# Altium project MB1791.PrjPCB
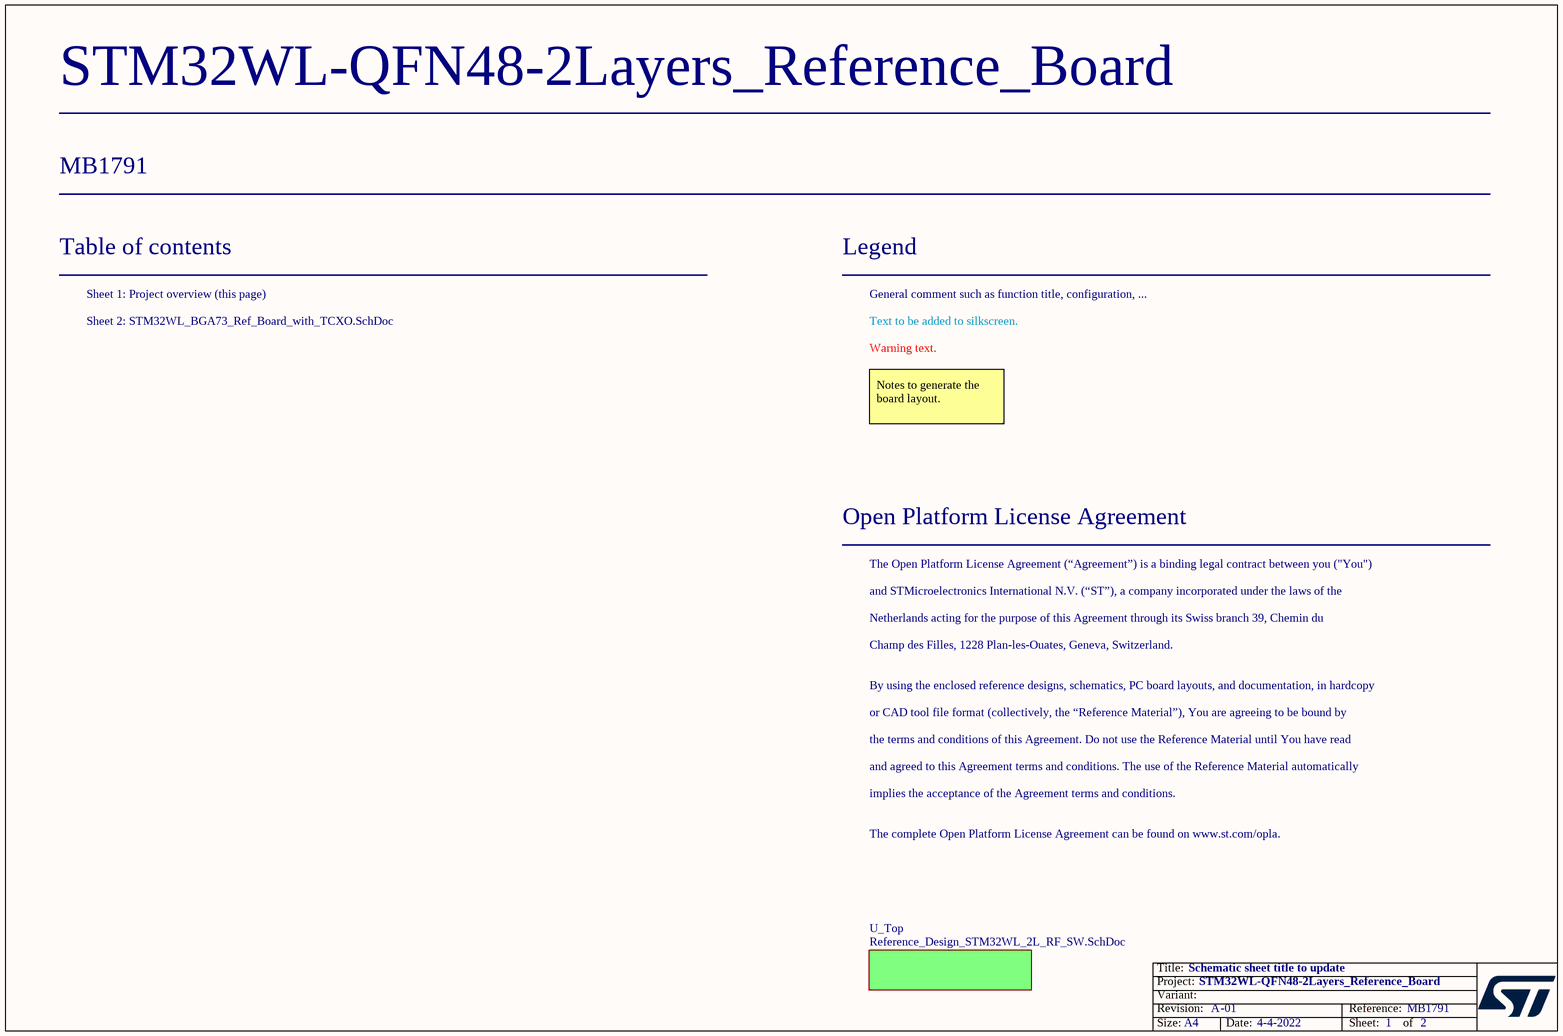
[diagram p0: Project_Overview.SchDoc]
Board_Assembly_Revision: 01; Board_Document_Date: 4-4-2022; Board_Name: STM32WL-QFN48-2Layers_Reference_Board; Board_PCB_Revision: A; Board_Reference: MB1791
2 sheets, 87 parts. Net scope: flat (ports and power ports of the same name join across sheets).
Board file: MB1791.PcbDoc
Sheets:
  Project_Overview.SchDoc
    U_Top = Reference_Design_STM32WL_2L_RF_SW.SchDoc

## Sheet Project_Overview.SchDoc: Schematic sheet title to update
size A4; Date: Not used; ApprovedBy: Not used; CheckedBy: Not used; Author: Not used; CompanyName: STMicroelectronics; DrawnBy: Not used; Engineer: Not used; Organization: Not used; Address1: Not used; Address2: Not used; Address3: Not used; Address4: Not used; DocumentNumber: Not used; Revision: Not used; SheetNumber: 1; SheetTotal: 2

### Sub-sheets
U_Top = Reference_Design_STM32WL_2L_RF_SW.SchDoc: no entries

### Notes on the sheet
- Table of contents
- Sheet 1: Project overview (this page)
- Legend
- General comment such as function title, configuration, ...
- Sheet 2: STM32WL_BGA73_Ref_Board_with_TCXO.SchDoc
- Text to be added to silkscreen.
- Warning text.
- Notes to generate the board layout.
- Open Platform License Agreement
- The Open Platform License Agreement (“Agreement”) is a binding legal contract between you ("You")
- and STMicroelectronics International N.V. (“ST”), a company incorporated under the laws of the
- Netherlands acting for the purpose of this Agreement through its Swiss branch 39, Chemin du
- Champ des Filles, 1228 Plan-les-Ouates, Geneva, Switzerland.
- By using the enclosed reference designs, schematics, PC board layouts, and documentation, in hardcopy
- or CAD tool file format (collectively, the “Reference Material”), You are agreeing to be bound by
- the terms and conditions of this Agreement. Do not use the Reference Material until You have read
- and agreed to this Agreement terms and conditions. The use of the Reference Material automatically
- implies the acceptance of the Agreement terms and conditions.
- The complete Open Platform License Agreement can be found on www.st.com/opla.

## Sheet Reference_Design_STM32WL_2L_RF_SW.SchDoc: STM32WL UFQFPN48 REF BOARD - Direct Tie - HP- 2L
size A3; DocumentNumber: MBxxxx; Revision: A; SheetNumber: 2; SheetTotal: 2
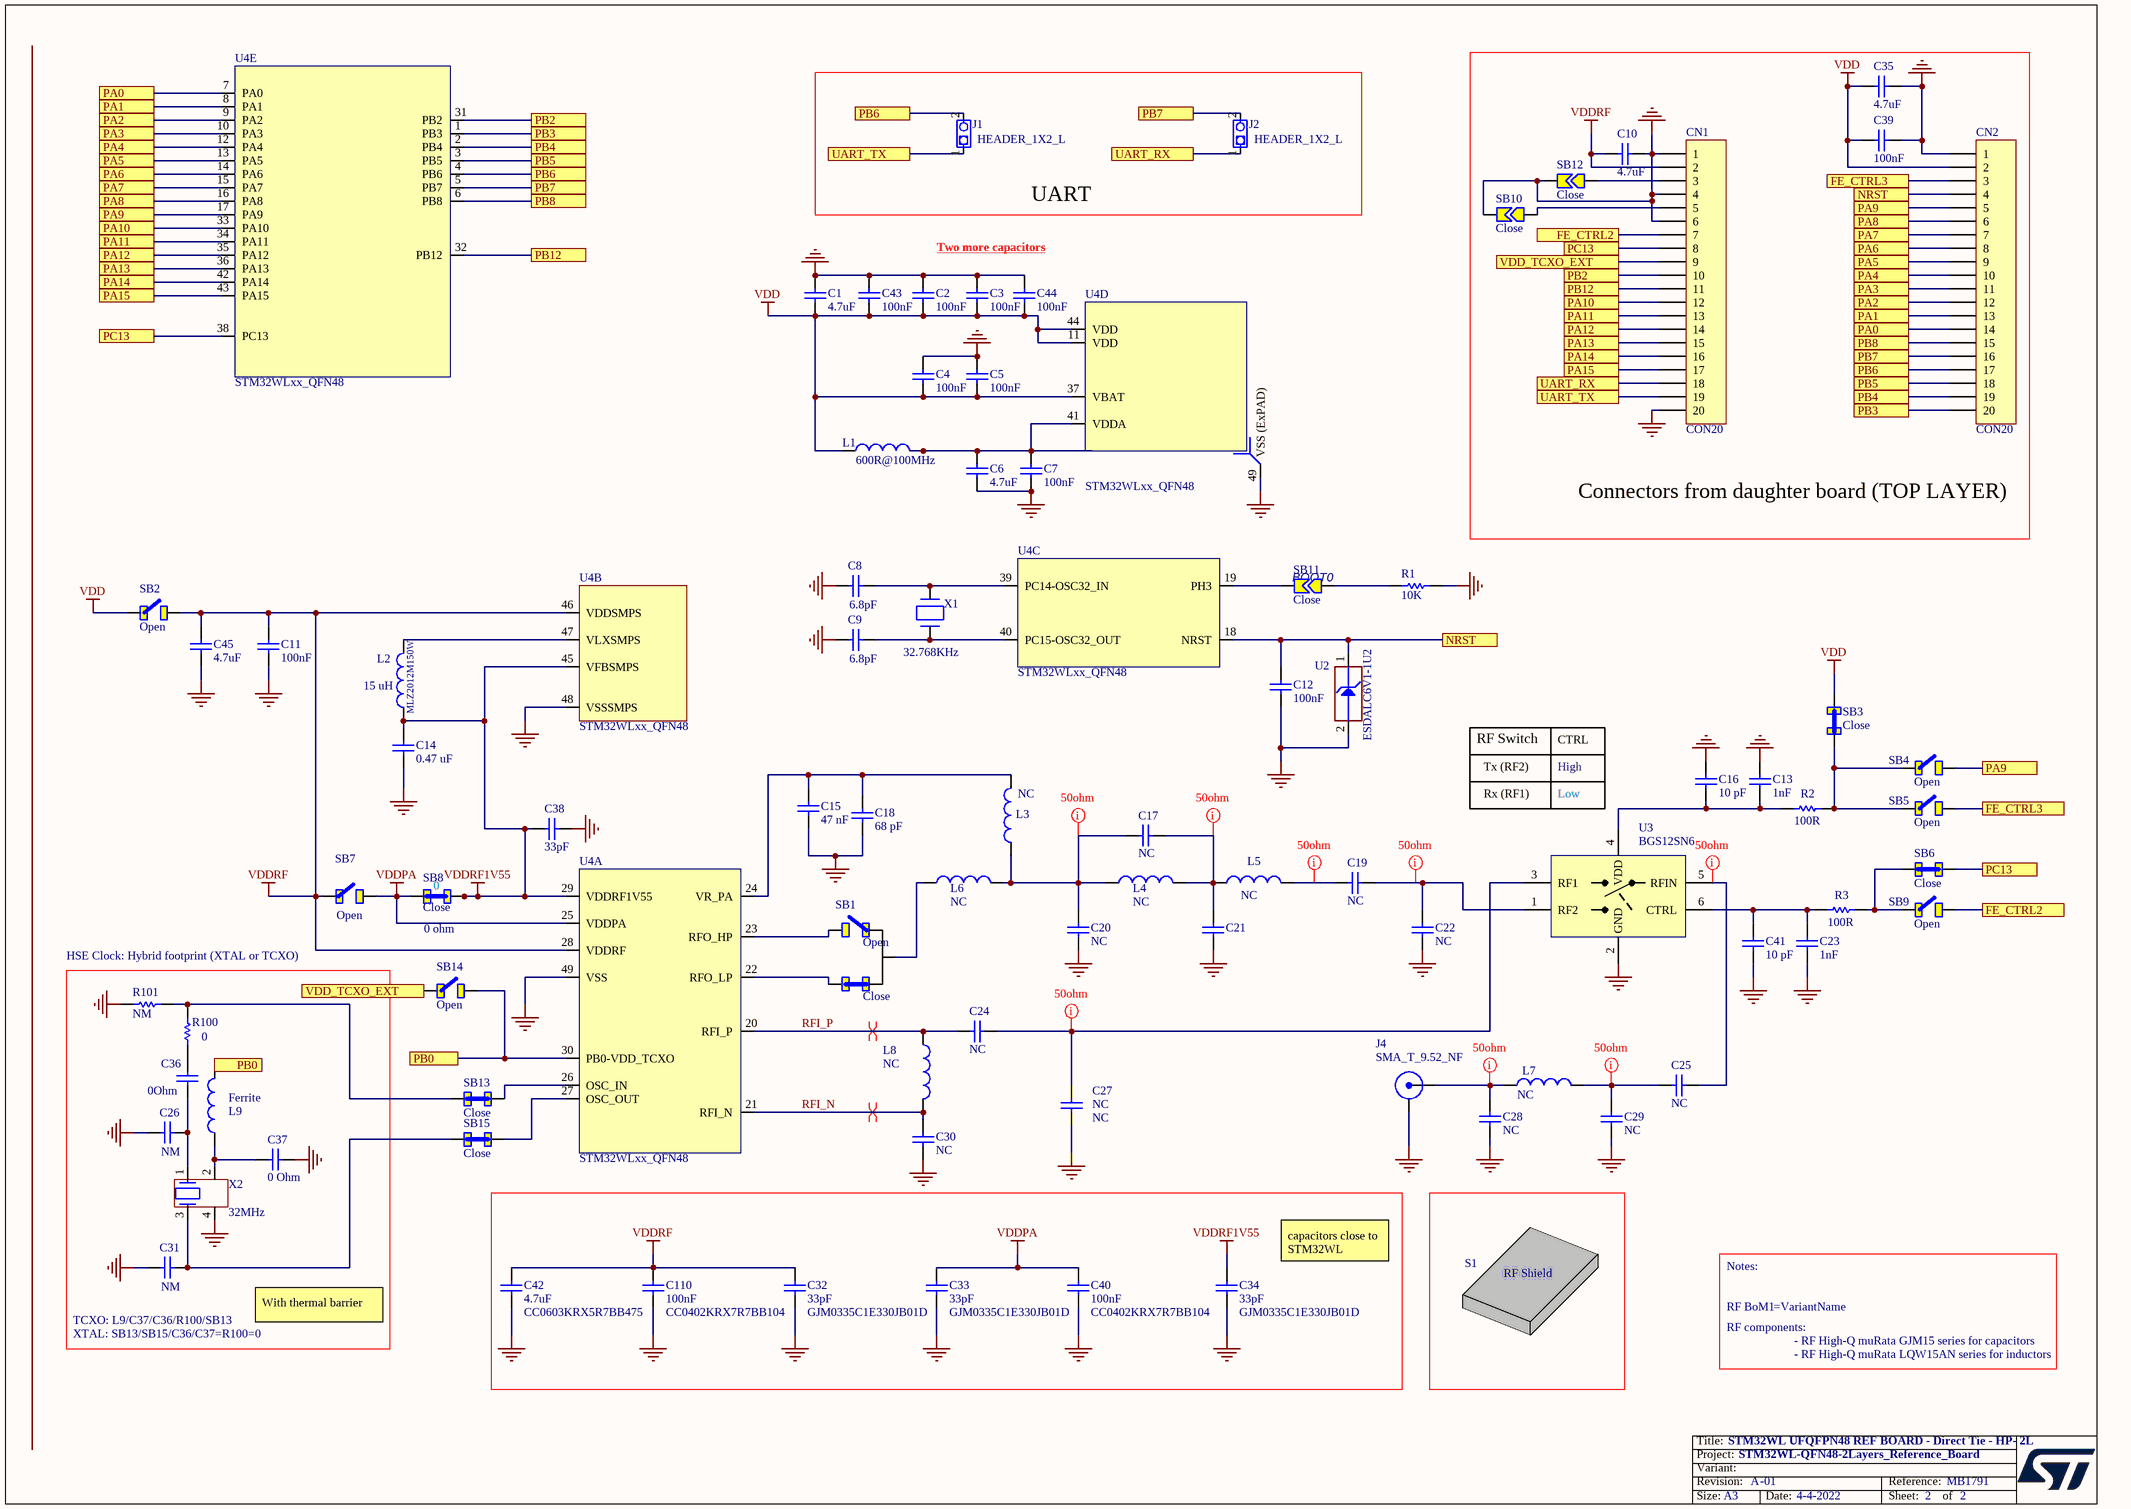
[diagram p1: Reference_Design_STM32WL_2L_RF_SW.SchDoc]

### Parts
C1  value 4.7uF  [CAPC1608X09N]
C2  value 100nF  [CAPC1005X06N]
C3  value 100nF  [0201]
C4  value 100nF  [CAPC1005X06N]
C5  value 100nF  [0201]
C6  value 4.7uF  [CAPC1608X09N]
C7  value 100nF  [CAPC1005X06N]
C8  value 6.8pF  [0402]  (hidden comment: Capacitor)
C9  value 6.8pF  [0402]  (hidden comment: Capacitor)
C10  value 4.7uF  [CAPC1608X09N]
C11  value 100nF  [CAPC1005X06N]
C12  value 100nF  [0402]
C13  value 1nF  [CAPC1005X06N]
C14  value 0.47 uF  [CAPC1608X09N]
C15  value 47 nF  [0402]
C16  value 10 pF  [CAPC1005X06N]
C17  value NC  [0402]
C18  value 68 pF  [0402]
C19  value NC  [0402]
C20  value NC  [0402]
C21  (no value)  [0402]
C22  value NC  [0402]
C23  value 1nF  [CAPC1005X06N]
C24  value NC  [0402]
C25  value NC  [CAPC1005X06N]
C26  value NM  [0402]  (hidden comment: Capacitor)
C27  NC  [CAPC1005X06N]
C28  value NC  [0402]  (hidden comment: MCD-00102)
C29  value NC  [0402]  (hidden comment: MCD-00102)
C30  value NC  [0402]
C31  value NM  [0402]  (hidden comment: Capacitor)
C32  value 33pF  Manufacturer_Part_Number: GJM0335C1E330JB01D  [0201]
C33  value 33pF  Manufacturer_Part_Number: GJM0335C1E330JB01D  [0201]
C34  value 33pF  Manufacturer_Part_Number: GJM0335C1E330JB01D  [0201]
C35  value 4.7uF  [CAPC1608X09N]
C36  value 0Ohm  [0402]
C37  value 0 Ohm  [0402]
C38  value 33pF  [0201]
C39  value 100nF  [CAPC1005X06N]
C40  value 100nF  Manufacturer_Part_Number: CC0402KRX7R7BB104  [CAPC1005X06N]
C41  value 10 pF  [CAPC1005X06N]
C42  value 4.7uF  Manufacturer_Part_Number: CC0603KRX5R7BB475  [CAPC1608X09N]
C43  value 100nF  [CAPC1005X06N]
C44  value 100nF  [0201]
C45  value 4.7uF  [CAPC1608X09N]
C110  value 100nF  Manufacturer_Part_Number: CC0402KRX7R7BB104  [CAPC1005X06N]
CN1  CON20  [CO_SAMTEC_TSW-120-07-x-S]
CN2  CON20  [CO_SAMTEC_TSW-120-07-x-S]
J1  HEADER_1X2_L  [CO_MOLEX_22-03-2021]
J2  HEADER_1X2_L  [CO_MOLEX_22-03-2021]
J4  SMA_T_9.52_NF  [CO_SAMTEC_SMA-J-P-ST-EMI]
L1  value 600R@100MHz  [INDC1608X95N]
L2  value 15 uH  Manufacturer_Part_Number: MLZ2012M150W  [INDC2012X13N]
L3  value NC  [0402_COIL]
L4  value NC  [0402_COIL]
L5  value NC  [0402_COIL]
L6  value NC  [0402_COIL]
L7  value NC  [0402_COIL]
L8  value NC  [0402_COIL]
L9  Ferrite  [IND_MURATA_LQW15A]
R1  value 10K  [RESC1608X05N]
R2  value 100R  [RESC1005X04N]
R3  value 100R  [RESC1005X04N]
R100  value 0  [R0402]  (hidden comment: Resistor)
R101  value NM  [R0402]  (hidden comment: Resistor)
RF_BoM1  RF-BOM  (value not drawn)  (mechanical)
S1  RF-Shield  (value not drawn)  (mechanical)
SB1  SB_3Pads  [SB3Pads_0402]  (value not drawn)
SB2  Open  [SB_0402]
SB3  Close  [SB_0402]
SB4  Open  [SB_0402]
SB5  Open  [SB_0402]
SB6  Close  [SB_0402]
SB7  Open  [SB_0402]
SB8  Close  value 0 ohm  [SB_0402]
SB9  Open  [SB_0402]
SB10  Close  [GC_0402]
SB11  Close  [GC_0402]
SB12  Close  [GC_0402]
SB13  Close  [SB_0402]
SB14  Open  [SB_0402]
SB15  Close  [SB_0402]
U2  Manufacturer_Part_Number: ESDALC6V1-1U2  [DIOM0603X03N]
U3  BGS12SN6  [SON40P70X40-6N]
U4  STM32WLxx_QFN48  [STM32WLxx_QFN48]  (parts A,B,C,D,E of 5)
X1  value 32.768KHz  [OSC_NDK_NX2012SA]  (hidden comment: XTAL_2_PINS)
X2  value 32MHz  [OSC_NDK_NX2016SA]

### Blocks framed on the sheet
Connectors from daughter board (TOP LAYER): C10 C35 C39 CN1 CN2 SB10 SB12
UART: J1 J2

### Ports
FE_CTRL2, FE_CTRL3, NRST, PA0, PA1, PA2, PA3, PA4, PA5, PA6, PA7, PA8, PA9, PA10, PA11, PA12, PA13, PA14, PA15, PB0, PB2, PB3, PB4, PB5, PB6, PB7, PB8, PB12, PC13, UART_RX, UART_TX, VDD_TCXO_EXT

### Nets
GND: C1.1 C2.1 C3.1 C4.1 C5.1 C6.2 C7.2 C8.2 C9.2 C10.2 C11.2 C12.2 C13.1 C14.2 C15.2 C16.1 C18.1 C20.2 C21.1 C22.1 C23.1 C26.2 C27.1 C28.2 C29.2 C30.1 C31.2 C32.1 C33.1 C34.1 C35.1 C37.1 C38.2 C39.2 C40.2 C41.2 C42.2 C43.1 C44.1 C45.2 C110.2 CN1.1 CN1.4 CN1.6 CN1.20 CN2.1 J4.2(Y) R1.1 R101.2 SB10.2 SB12.2 U2.2(GND) U3.2(GND) U4.48(VSSSMPS) U4.49(VSS_(ExPAD)) X2.4
VDD: C1.2 C2.2 C3.2 C4.2 C5.2 C35.2 C39.1 C43.2 C44.2 CN2.2 L1.1 SB2.2 SB3.1 U4.11(VDD) U4.37(VBAT) U4.44(VDD)
VDDPA: C33.2 C40.1 SB7.1 SB8.2 U4.25(VDDPA)
VDDRF: C10.1 C11.1 C32.2 C42.1 C45.1 C110.1 CN1.2 SB2.1 SB7.2 U4.28(VDDRF) U4.46(VDDSMPS)
VDDRF1V55: C14.1 C34.2 C38.1 L2.1 SB8.1 U4.29(VDDRF1V55) U4.45(VFBSMPS)
FE_CTRL2: CN1.7 SB9.1 ; port FE_CTRL2
FE_CTRL3: CN2.3 SB5.1 ; port FE_CTRL3
NRST: C12.1 CN2.4 U2.1(IO1) U4.18(NRST) ; port NRST
PA0: CN2.14 U4.7(PA0) ; port PA0
PA1: CN2.13 U4.8(PA1) ; port PA1
PA2: CN2.12 U4.9(PA2) ; port PA2
PA3: CN2.11 U4.10(PA3) ; port PA3
PA4: CN2.10 U4.12(PA4) ; port PA4
PA5: CN2.9 U4.13(PA5) ; port PA5
PA6: CN2.8 U4.14(PA6) ; port PA6
PA7: CN2.7 U4.15(PA7) ; port PA7
PA8: CN2.6 U4.16(PA8) ; port PA8
PA9: CN2.5 SB4.1 U4.17(PA9) ; port PA9
PA10: CN1.12 U4.33(PA10) ; port PA10
PA11: CN1.13 U4.34(PA11) ; port PA11
PA12: CN1.14 U4.35(PA12) ; port PA12
PA13: CN1.15 U4.36(PA13) ; port PA13
PA14: CN1.16 U4.42(PA14) ; port PA14
PA15: CN1.17 U4.43(PA15) ; port PA15
PB0: L9.2 SB14.1 U4.30(PB0-VDD_TCXO) ; port PB0
PB2: CN1.10 U4.31(PB2) ; port PB2
PB3: CN2.20 U4.1(PB3) ; port PB3
PB4: CN2.19 U4.2(PB4) ; port PB4
PB5: CN2.18 U4.3(PB5) ; port PB5
PB6: CN2.17 J1.2 U4.4(PB6) ; port PB6
PB7: CN2.16 J2.2 U4.5(PB7) ; port PB7
PB8: CN2.15 U4.6(PB8) ; port PB8
PB12: CN1.11 U4.32(PB12) ; port PB12
PC13: CN1.8 SB6.1 U4.38(PC13) ; port PC13
RFI_N: C30.2 L8.2 U4.21(RFI_N)
RFI_P: C24.1 L8.1 U4.20(RFI_P)
UART_RX: CN1.18 J2.1 ; port UART_RX
UART_TX: CN1.19 J1.1 ; port UART_TX
VDD_TCXO_EXT: CN1.9 SB14.2 ; port VDD_TCXO_EXT
NetC6_1: C6.1 C7.1 L1.2 U4.41(VDDA)
NetC8_1: C8.1 U4.39(PC14-OSC32_IN) X1.2(X2)
NetC9_1: C9.1 U4.40(PC15-OSC32_OUT) X1.1(X1)
NetC13_2: C13.2 C16.2 R2.1 U3.4(VDD)
NetC15_1: C15.1 C18.2 L3.1 U4.24(VR_PA)
NetC17_1: C17.1 C20.1 L3.2 L4.1 L6.2
NetC17_2: C17.2 C21.2 L4.2 L5.1
NetC19_1: C19.1 C22.2 U3.1(RF2)
NetC19_2: C19.2 L5.2
NetC23_2: C23.2 C41.1 R3.1 U3.6(CTRL)
NetC24_2: C24.2 C27.2 U3.3(RF1)
NetC25_1: C25.1 U3.5(RFIN)
NetC25_2: C25.2 C29.1 L7.1
NetC26_1: C26.1 C36.2 X2.1
NetC28_1: C28.1 J4.1(X) L7.2
NetC31_1: C31.1 SB15.2 X2.3
NetC36_1: C36.1 R100.2
NetC37_2: C37.2 L9.1 X2.2
NetCN1_3: CN1.3 SB12.1
NetCN1_5: CN1.5 SB10.1
NetL2_2: L2.2 U4.47(VLXSMPS)
NetL6_1: L6.1 SB1.2
NetR1_2: R1.2 SB11.1
NetR2_2: R2.2 SB3.2 SB4.2 SB5.2
NetR3_2: R3.2 SB6.2 SB9.2
NetR100_1: R100.1 R101.1 SB13.2
NetSB1_1: SB1.1 U4.23(RFO_HP)
NetSB1_3: SB1.3 U4.22(RFO_LP)
NetSB11_2: SB11.2 U4.19(PH3)
NetSB13_1: SB13.1 U4.26(OSC_IN)
NetSB15_1: SB15.1 U4.27(OSC_OUT)

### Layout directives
net class 50ohm: NetC17_1, NetC17_2, NetC19_1, NetC19_2, NetC24_2, NetC25_1, NetC25_2, NetC28_1
differential pair: RFI_N, RFI_P

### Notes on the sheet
- Two more capacitors
- (near SB11) BOOT0
- RF Switch
- Tx (RF2)
- CTRL
- High
- Rx (RF1)
- Low
- HSE Clock: Hybrid footprint (XTAL or TCXO)
- capacitors close to STM32WL
- (near C31) TCXO: L9/C37/C36/R100/SB13
- With thermal barrier
- Notes:
- XTAL: SB13/SB15/C36/C37=R100=0
- RF components:
- (near RF_BoM1) - RF High-Q muRata GJM15 series for capacitors
- (near RF_BoM1) - RF High-Q muRata LQW15AN series for inductors

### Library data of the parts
C1 C6 C10 C35 C45 = MCD-00009: Capacitor, MLCC, 4.7uF, 16V, X5R, 10%, 0603, T=0.8mm; Manufacturer_Part_Number: CC0603KRX5R7BB475; Manufacturer: YAGEO
C2 C4 C7 C11 C12 C39 C43 = MCD-00102: Capacitor, MLCC, 100nF, 16V, X7R, 10%, 0402, T=0,5mm; Manufacturer_Part_Number: CC0402KRX7R7BB104; Manufacturer: YAGEO
C3 C5 C44 = MCD-00102: Multilayer Ceramic Capacitors MLCC - SMD/SMT 0201 25VDC 0.1uF 10% X5R 0.3mm; Manufacturer_Part_Number: C0603X5R1E104K030BB; Manufacturer: TDK
C8 C9 C26 C31 = MCD-00003: Capacitor, MLCC, 6.8pF, 50V, NPO, +-0.1pF, 0402, T=0.5mm; Manufacturer_Part_Number: GRM1555C1H6R8BA01; Manufacturer: MURATA
C13 C23 = MCD-00198: Capacitor, MLCC, 1nF, 16V, X7R, 10%, 0402, T=0.5mm; Manufacturer_Part_Number: CC0402KRX7R7BB102; Manufacturer: YAGEO
C14 = MCD-00009: Capacitor, MLCC, 4.7 uF, 16V, X5R, 10%, 0603, T=0.8mm; Manufacturer_Part_Number: CC0603KRX5R7BB474; Manufacturer: YAGEO
C15 = MCD-01123: Capacitor, MLCC,47nF, 16V, X7R, 10%, 0402, T=0.5mm; Manufacturer_Part_Number: GCM155R71E473KA55; Manufacturer: MURATA
C16 C41 = MCD-00102: Capacitor, MLCC, 10 pF; Manufacturer_Part_Number: GJM1555C1H100FB01D; Manufacturer: MURATA
C17 C19 C22 C24 C25 C27 C30 = MCD-01123: RF Capacitor
C18 = MCD-01123: Capacitor, MLCC,68pF, 50V, C0G, 1%, 0402, T=0.5mm; Manufacturer_Part_Number: GCM1555C1H680JA16; Manufacturer: MURATA
C20 C28 C29 = MCD-00102: RF Capacitor
C21 = MCD-00015: RF Capacitor
C32-C34 = MCD-00277: Multilayer Ceramic Capacitors MLCC - SMD/SMT 0201 33pF 25volts C0G 5%; Manufacturer: MURATA
C36 C37 = MCD-00277: Capacitor, MLCC, 33pF, 50V, NPO, 2%, 0402, T=0,5mm; Manufacturer_Part_Number: RCS04020000Z0ED; Manufacturer: Vishay / Dale
C38 = MCD-01123: Multilayer Ceramic Capacitors MLCC - SMD/SMT 0201 33pF 25volts C0G 5%; Manufacturer_Part_Number: GJM0335C1E330JB01D; Manufacturer: MURATA
C40 C110 = MCD-00102: Capacitor, MLCC, 100nF, 16V, X7R, 10%, 0402, T=0,5mm; Manufacturer: YAGEO
C42 = MCD-00009: Capacitor, MLCC, 4.7uF, 16V, X5R, 10%, 0603, T=0.8mm; Manufacturer: YAGEO
CN1 CN2 = CON20: Connector right-angle, pitch 2.54mm, 20 contacts; Manufacturer: SAMTEC; Manufacturer_Part_Number: TSW-120-07-L-S
J4 = SMA_T_9.52_NF: SMA Jack, Edge Mount, 50 Ohms; Manufacturer: Taoglas; Manufacturer_Part_Number: EMPCB.SMAFSTJ.B.HT
L1 = MCD-00047: SMD Chip ferrite bead, 600R@100MHz +/-25%, 350mA, 500mohm DC, 0603, T=0.8mm; Manufacturer_Part_Number: BK1608HS601-T; Manufacturer: Taiyo Yuden
L2 = MCD-01433: MLZ2012 Multilayer Shielded Inductor 15 uH, ±5%; Manufacturer: TDK
L3-L8 = MCD-01330: RF Inductor
L9 = MCD-01330: Inductor, 3.9nH, +-0.1nH, 750mA, 0402; Manufacturer: MURATA; Value: LQW15AN3N9B00#; Provided_By: SUBCO; Initial_Board_Reference: MB1402
R1 = MCD-00220: Resistor,10K,0603,1%,1/10W; Manufacturer_Part_Number: RC0603FR-0710KL; Manufacturer: YAGEO
R2 R3 = MCD-00119: Resistor,100R,0402,1%,1/16W; Manufacturer_Part_Number: RC0402FR-07100RL; Manufacturer: YAGEO
R100 R101 = MCD-00052: Resistor,0R,0402,5%,1/16W; Manufacturer_Part_Number: RC0402JR-070RL; Manufacturer: YAGEO; Provided_By: SUBCO; Initial_Board_Reference: MB1274
S1 = RF-Shield: RF Shield Frame + Cover without apertures; Manufacturer: Masach Tech; Manufacturer_Part_Number: MS409-10
SB1 = SB_3Pads: Solder Bridge
SB2 SB4 SB5 SB9 SB14 = SB_Open: Solder Bridge Open [0402] (Unpopulated)
SB3 SB6 = SB_0Ohm: Solder Bridge 0R [0402] (Populated with 0 Ohm); Manufacturer: Vishay / Dale; Manufacturer_Part_Number: RCS04020000Z0ED; VALUE: 0 ohm
SB7 = SB_Open_1: Solder Bridge Open [0402] (Unpopulated); Manufacturer: Vishay / Dale; Manufacturer_Part_Number: RCS04020000Z0ED
SB8 = SB_Close_1: Solder Bridge 0R [0402] (Populated with 0 Ohm); Manufacturer: Vishay / Dale; Manufacturer_Part_Number: RCS04020000Z0ED
SB10 SB12 = Strap2: Solder Jumper - Open; Manufacturer: Vishay / Dale; Manufacturer_Part_Number: RCS04020000Z0ED
SB11 = Strap2: Solder Jumper - Close; Manufacturer: Vishay / Dale; Manufacturer_Part_Number: RCS04020000Z0ED
SB13 SB15 = SB_0Ohm: Solder Bridge 0R [0402] (Populated with 0 Ohm); Manufacturer: Vishay / Dale; Manufacturer_Part_Number: RCS04020000Z0ED; VALUE: 0
U2 = MCD-00170: ESD protection 6V1; Manufacturer: STMICROELECTRONICS
U3 = BGS12SN6: DC switch - Ultra-Low  SPDT analog switch; Manufacturer: INFINEON
U4 = STM32WLxx_QFN48: STM32WL ARM MCU Multiprotocol LPWAN 32-bit Arm Cortex-M4 MCUs LoRa (G)FSK-MSK BPSK; Manufacturer_Part_Number: STM32WLE5CC; Manufacturer: STMicroelectronics
X1 = MCD-01479: Crystal 32.768kHz, 6pF, -+20PPM, R=80K, SMD; Manufacturer_Part_Number: NX2012SA 32.768KHz EXS00A-MU00527; Manufacturer: NDK
X2 = MCD-01446: Crystal 32 MHz, 8pF, -+10 PPM, R=60Ω, SMD; Manufacturer_Part_Number: NX2016SA 32MHz EXS00A-CS06465; Manufacturer: NDK

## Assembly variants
LowBand_HighPower: not fitted C20; alternate parts SB7 -> SB_Close_1, SB8 -> SB_Open_1, SB1 -> SB_3Pads_HP
HighBand_LowPower: not fitted C28 C29; alternate parts SB8 -> SB_Close_1
HighBand_HighPower: not fitted C28 C29; alternate parts SB7 -> SB_0Ohm_1, SB8 -> SB_Open_1, SB1 -> SB_3Pads_HP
